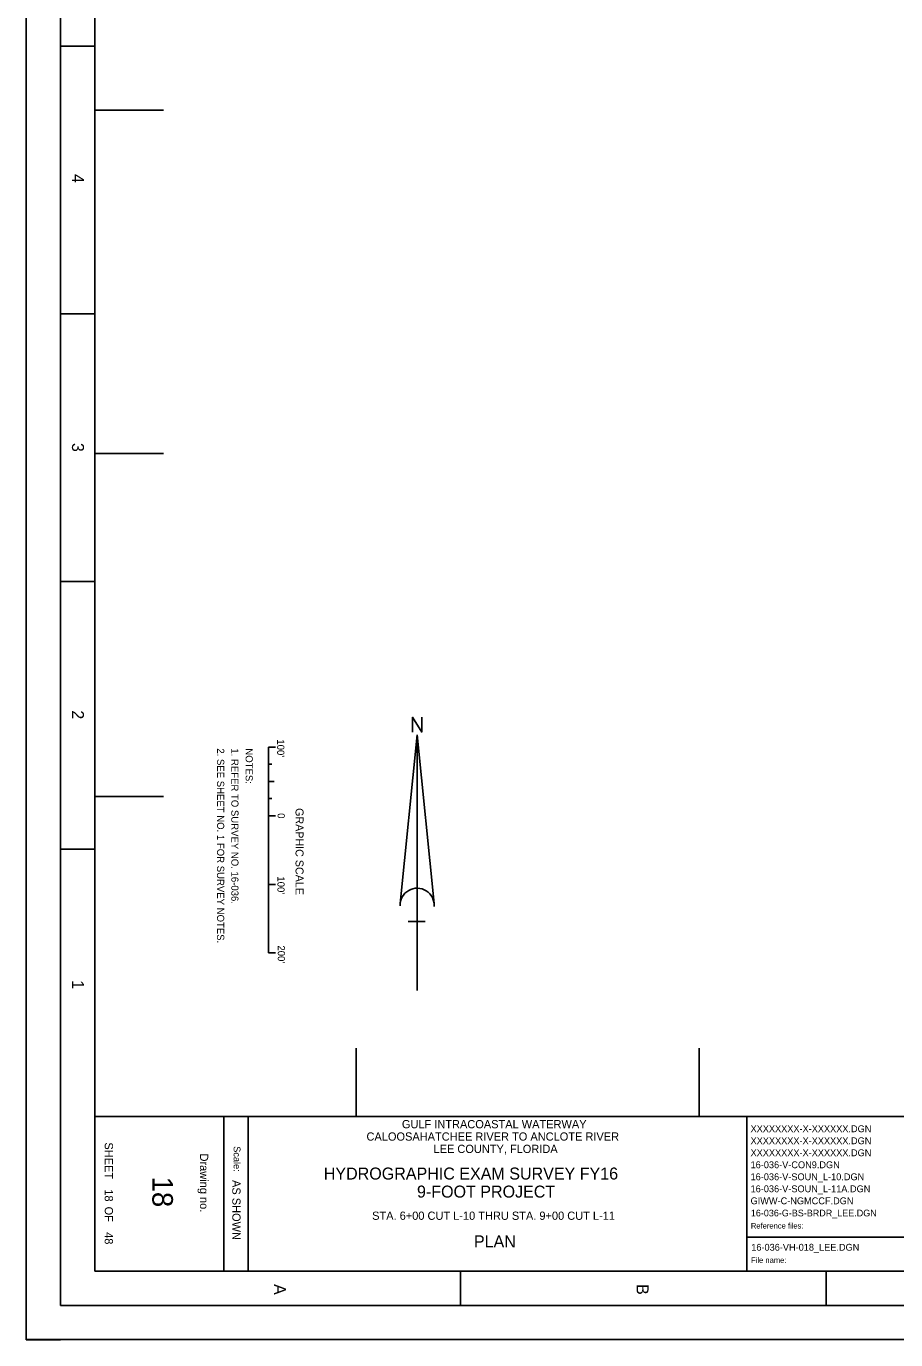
# Model space of a CAD drawing. Extents: x 604519 to 607919, y 792708 to 797108.
# Drawn here: x 604519 to 605787, y 792708 to 794622 of the extents above; entities that cross this region are included whole.
import ezdxf

# ---------------------------------------------------------------- set-up
doc = ezdxf.new("R2010")
doc.units = 0
for name, color, linetype in [('G-ANNO-NPLT', 7, 'Continuous'), ('G-ANNO-TEXT-DRWG', 7, 'Continuous'), ('G-ANNO-TEXT-PROJ', 7, 'Continuous'), ('G-ANNO-TEXT-TTLB', 7, 'Continuous'), ('G-ANNO-TTLB', 7, 'Continuous'), ('V-ANNO-NOTE', 7, 'Continuous'), ('V-ANNO-SYMB', 7, 'Continuous'), ('V-TOPO-COOR-STAT', 7, 'Continuous')]:
    doc.layers.add(name, color=color, linetype=linetype)

msp = doc.modelspace()

# ---------------------------------------------------------------- linework, layer by layer
at = {"layer": 'G-ANNO-NPLT'}
msp.add_lwpolyline([(607918.9, 797108.4), (607918.9, 792708.4), (604519, 792708.4), (604519, 797108.4)], close=True, dxfattribs=at)
msp.add_lwpolyline([(604569, 792708.3), (604519, 792708.3), (604519, 792758.3)], dxfattribs=at)
at = {"layer": 'G-ANNO-TTLB'}
for p, q in [((604569, 794593.4), (604619, 794593.4)), ((604569, 794203.4), (604619, 794203.4)), ((604569, 793813.4), (604619, 793813.4)), ((604569, 793423.4), (604619, 793423.4)), ((607818.9, 793033.4), (604619, 793033.4)), ((604807, 793033.4), (604807, 792808.4)), ((604842.7, 793033.4), (604842.7, 792808.4)), ((605569.7, 793033.4), (605569.7, 792808.4)), ((605921.1, 792857.7), (605569.7, 792857.7)), ((605152.2, 792758.4), (605152.2, 792808.4)), ((605685.5, 792758.4), (605685.5, 792808.4))]:
    msp.add_line(p, q, dxfattribs=at)
for points in [[(604569, 797058.4), (604569, 792758.4), (607868.9, 792758.4), (607868.9, 797058.4)], [(607818.9, 792808.4), (607818.9, 796933.4), (604619, 796933.4), (604619, 792808.4)]]:
    msp.add_lwpolyline(points, close=True, dxfattribs=at)
at = {"layer": 'V-ANNO-NOTE'}
for p, q in [((604872.1, 793571.9), (604872.1, 793271.9)), ((604872.1, 793571.9), (604882.5, 793571.9)), ((604872.1, 793546.9), (604876.9, 793546.9)), ((604872.1, 793521.9), (604880.6, 793521.9)), ((604872.1, 793496.9), (604876.9, 793496.9)), ((604872.1, 793471.9), (604882.5, 793471.9)), ((604872.1, 793471.9), (604877.1, 793471.9)), ((604872.1, 793471.9), (604882.5, 793471.9)), ((604872.1, 793371.9), (604882.5, 793371.9)), ((604872.1, 793271.9), (604882.5, 793271.9))]:
    msp.add_line(p, q, dxfattribs=at)
at = {"layer": 'V-ANNO-SYMB'}
for p, q in [((605064.2, 793343.9), (605088.9, 793589.7)), ((605088.9, 793217.3), (605088.9, 793589.7)), ((605113.6, 793343.9), (605088.9, 793589.7)), ((605100.7, 793317.9), (605075.9, 793317.9))]:
    msp.add_line(p, q, dxfattribs=at)
msp.add_lwpolyline([(605082, 793593.7), (605082, 793615.4), (605095.6, 793593.7), (605095.6, 793615.4)], dxfattribs=at)
msp.add_arc((605088.9, 793341.5), 24.8, 355.2984, 182.0673, dxfattribs=at)
at = {"layer": 'V-TOPO-COOR-STAT'}
for p, q in [((604620.4, 794500), (604719, 794500)), ((604620.4, 794000), (604719, 794000)), ((604620.4, 793500), (604719, 793500)), ((605000, 793033.4), (605000, 793133.4)), ((605500, 793033.4), (605500, 793133.4))]:
    msp.add_line(p, q, dxfattribs=at)

# ---------------------------------------------------------------- texts
at = {"layer": 'G-ANNO-TEXT-DRWG'}
for s, height, rotation, p in [('XXXXXXXX-X-XXXXXX.DGN', 10, 360, (605575.1, 793010.7)), ('XXXXXXXX-X-XXXXXX.DGN', 10, 360, (605575.1, 792993.2)), ('XXXXXXXX-X-XXXXXX.DGN', 10, 360, (605575.1, 792975.7)), ('16-036-V-CON9.DGN', 10, 360, (605575.1, 792958.2)), ('16-036-V-SOUN_L-10.DGN', 10, 360, (605575.1, 792940.7)), ('18', 30, 270, (604702.8, 792946)), ('16-036-V-SOUN_L-11A.DGN', 10, 360, (605575.1, 792923.2)), (' 18          48', 12, 270, (604633.4, 792931.9)), ('GIWW-C-NGMCCF.DGN', 10, 360, (605575.1, 792905.7)), ('STA. 6+00 CUT L-10 THRU STA. 9+00 CUT L-11', 12, 360, (605023.3, 792883)), ('PLAN', 17.5, 360, (605171.7, 792842.8)), ('16-036-VH-018_LEE.DGN', 10, 360, (605576.1, 792838))]:
    msp.add_text(s, height=height, rotation=rotation, dxfattribs=at).set_placement(p)
at = {"layer": 'G-ANNO-TEXT-PROJ'}
for s, height, p in [('GULF INTRACOASTAL WATERWAY', 12, (605066.7, 793016.4)), ('CALOOSAHATCHEE RIVER TO ANCLOTE RIVER', 12, (605015.1, 792998.4)), ('LEE COUNTY, FLORIDA', 12, (605112.8, 792980.4)), ('HYDROGRAPHIC EXAM SURVEY FY16', 17.5, (604952.8, 792941.7)), ('9-FOOT PROJECT', 17.5, (605088.7, 792915.4)), ('16-036-G-BS-BRDR_LEE.DGN', 9.8, (605575.5, 792888))]:
    msp.add_text(s, height=height, rotation=360, dxfattribs=at).set_placement(p)
at = {"layer": 'G-ANNO-TEXT-TTLB'}
for s, height, rotation, p in [('SHEET         OF', 12, 270, (604633.4, 792995.9)), ('Scale:', 10, 270, (604821.3, 792990.3)), ('Drawing no.', 12, 270, (604772.3, 792979.6)), ('AS SHOWN', 12, 270, (604819.4, 792941)), ('Reference files:', 8, 360, (605575.5, 792870.3)), ('File name:', 8, 360, (605575.8, 792820.3))]:
    msp.add_text(s, height=height, rotation=rotation, dxfattribs=at).set_placement(p)
at = {"layer": 'G-ANNO-TTLB'}
for s, p in [('4', (604585.6, 794407.1)), ('3', (604585.6, 794015.2)), ('2', (604585.6, 793625.5)), ('1', (604585.6, 793232.3)), ('A', (604880.1, 792789.4)), ('B', (605408.9, 792789.4))]:
    msp.add_text(s, height=17.5, rotation=270, dxfattribs=at).set_placement(p)
at = {"layer": 'V-ANNO-NOTE'}
for s, height, p in [("100'", 10.42, (604884.8, 793583.2)), ('2. SEE SHEET NO. 1 FOR SURVEY NOTES.', 10.416, (604797.2, 793570.1)), ('1. REFER TO SURVEY NO. 16-036.', 10.416, (604818, 793570.1)), ('NOTES:', 10.42, (604838.8, 793570.1)), ('0', 10.4, (604885.5, 793475.6)), ('GRAPHIC SCALE', 11.666, (604911.6, 793483)), ("100'", 10.42, (604885.2, 793383.5)), ("200'", 10.42, (604885.7, 793282.9))]:
    msp.add_text(s, height=height, rotation=270, dxfattribs=at).set_placement(p)

doc.saveas('drawing.dxf')
